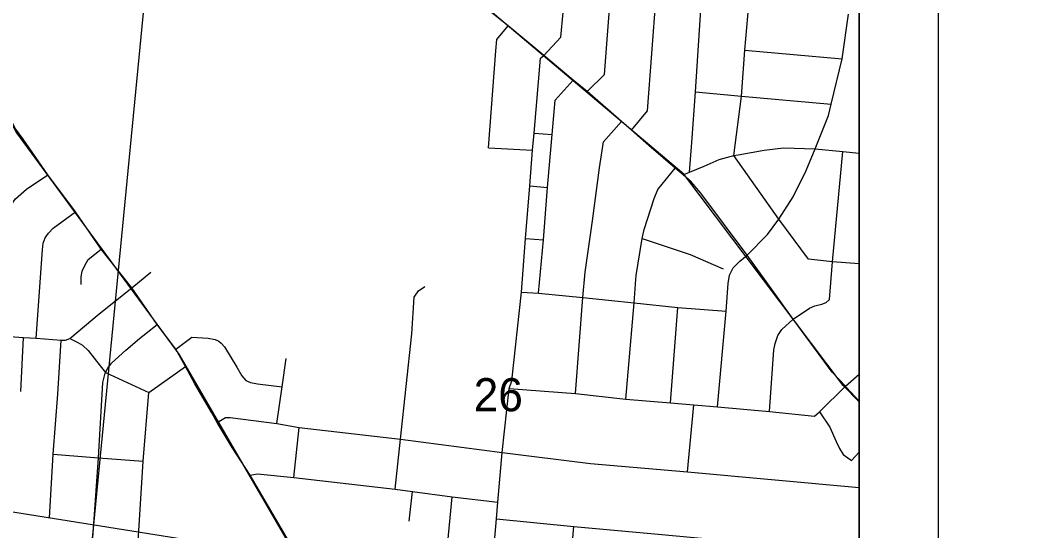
# Model space of a CAD drawing. Extents: x 0 to 34, y 0 to 22.
# Drawn here: x 7.838 to 9.127, y 16.149 to 16.794 of the extents above; entities that cross this region are included whole.
import ezdxf

# ---------------------------------------------------------------- set-up
doc = ezdxf.new("R2010")
doc.units = 0
for name, color, linetype in [('Default', 7, 'Continuous'), ('GM_X_City_Street', 7, 'Continuous'), ('GM_X_County_Road', 7, 'Continuous'), ('GM_X_Rail_Line', 7, 'Continuous'), ('GM_X_Section', 7, 'Continuous'), ('GM_X_Section_Text', 7, 'Continuous'), ('GM_X_State_Route', 7, 'Continuous'), ('GM_X_Township_Road', 7, 'Continuous'), ('SH_Data', 7, 'Continuous'), ('SH_Text', 7, 'Continuous')]:
    doc.layers.add(name, color=color, linetype=linetype)

msp = doc.modelspace()

# ---------------------------------------------------------------- linework, layer by layer
at = {"layer": 'Default'}
msp.add_lwpolyline([(8.9, 15.7814), (8.9, 16.8048), (8.0016, 16.8868), (7.9035, 15.8736)], close=True, dxfattribs=at)
at = {"layer": 'GM_X_City_Street'}
for p, q in [((8.7551, 16.7564), (8.8784, 16.7457)), ((8.4884, 16.6515), (8.5115, 16.6501)), ((8.6852, 16.6021), (8.688, 16.6398)), ((8.4308, 16.6329), (8.4866, 16.6299)), ((8.4829, 16.5851), (8.5056, 16.5827)), ((8.4774, 16.5183), (8.5004, 16.5168)), ((7.9795, 16.4558), (8.0034, 16.4757)), ((8.6609, 16.3104), (8.6702, 16.4312)), ((7.839, 16.3248), (7.8423, 16.3933)), ((8.9, 16.3125), (8.8838, 16.33)), ((8.6825, 16.2232), (8.6904, 16.308)), ((8.1844, 16.2161), (8.1912, 16.2795)), ((8.3305, 16.1607), (8.3347, 16.1985)), ((8.5321, 16.0763), (8.5389, 16.154))]:
    msp.add_line(p, q, dxfattribs=at)
for points in [[(8.9, 16.4865), (8.8662, 16.4889), (8.8359, 16.4923), (8.7983, 16.5429), (8.7412, 16.6234), (8.751, 16.6985), (8.7551, 16.7564), (8.7604, 16.814), (8.776, 16.9853), (8.7868, 17.1123), (8.7916, 17.1766), (8.8011, 17.2471), (8.8108, 17.3575), (8.8134, 17.4882), (8.8144, 17.504), (8.8153, 17.5125), (8.8617, 17.5828), (8.8723, 17.6093)], [(8.5554, 16.7041), (8.5774, 16.726), (8.5855, 16.8312), (8.5988, 17.0025), (8.6063, 17.1111), (8.6106, 17.167)], [(8.6116, 16.6556), (8.6318, 16.6797), (8.6429, 16.8253), (8.6561, 16.9964), (8.6684, 17.1592)], [(8.6978, 16.7817), (8.7003, 16.8196), (8.7037, 16.8601)], [(8.8838, 16.33), (8.8824, 16.3315), (8.8656, 16.3492), (8.8164, 16.4162), (8.7823, 16.464), (8.7583, 16.4972), (8.6994, 16.5756), (8.6873, 16.59), (8.6771, 16.5987), (8.667, 16.6073), (8.6336, 16.6362), (8.6116, 16.6556), (8.5992, 16.6662), (8.5554, 16.7041), (8.538, 16.7187), (8.5006, 16.7499), (8.4555, 16.7875), (8.3773, 16.8503)], [(8.5006, 16.7499), (8.5224, 16.7729), (8.5281, 16.8359)], [(8.7583, 16.4972), (8.784, 16.5233), (8.7983, 16.5429), (8.8163, 16.5712), (8.8327, 16.6043), (8.844, 16.6316), (8.861, 16.6738), (8.8646, 16.6881), (8.8784, 16.7457), (8.8865, 16.8022)], [(8.4308, 16.6329), (8.4401, 16.7558), (8.4411, 16.7699), (8.4555, 16.7875)], [(8.688, 16.6398), (8.6926, 16.704), (8.6978, 16.7817)], [(8.4086, 15.8203), (8.4148, 15.879), (8.42, 15.9362), (8.4311, 16.0521), (8.4407, 16.1639), (8.4425, 16.1849), (8.4481, 16.2479), (8.4567, 16.3286), (8.4603, 16.3382), (8.4723, 16.4504), (8.4774, 16.5183), (8.4829, 16.5851), (8.4866, 16.6299), (8.4884, 16.6515), (8.4965, 16.7464), (8.5006, 16.7499)], [(8.4942, 16.4491), (8.5004, 16.5168), (8.5056, 16.5827), (8.5115, 16.6501), (8.5152, 16.6934), (8.538, 16.7187)], [(8.6926, 16.704), (8.751, 16.6985), (8.8646, 16.6881)], [(8.5407, 16.3224), (8.5502, 16.4438), (8.5531, 16.476), (8.5622, 16.5409), (8.5712, 16.6078), (8.5763, 16.6405), (8.5992, 16.6662)], [(8.6771, 16.5987), (8.6852, 16.6021), (8.7038, 16.6099), (8.7225, 16.6183), (8.7412, 16.6234), (8.7469, 16.6244), (8.7795, 16.6302), (8.8042, 16.633), (8.844, 16.6316), (8.8791, 16.6286), (8.9, 16.6265)], [(8.7865, 16.2995), (8.7918, 16.3776), (8.7934, 16.3856), (8.797, 16.3959), (8.8021, 16.4035), (8.8164, 16.4162), (8.8369, 16.4302), (8.8437, 16.4333), (8.8526, 16.4354), (8.8579, 16.4375), (8.8621, 16.4412), (8.8662, 16.4889), (8.8791, 16.6286)], [(7.7859, 16.2596), (7.7949, 16.3964), (7.8011, 16.4591), (7.8063, 16.5164), (7.8121, 16.537), (7.8198, 16.5512), (7.832, 16.5685), (7.8462, 16.5808), (7.8732, 16.5991)], [(8.6046, 16.3153), (8.6152, 16.437), (8.6171, 16.4664), (8.6176, 16.4717), (8.6252, 16.5182), (8.6276, 16.5296), (8.6404, 16.569), (8.6452, 16.5804), (8.667, 16.6073)], [(7.2902, 16.5568), (7.2963, 16.5565), (7.3438, 16.5259), (7.4102, 16.4873), (7.4406, 16.4692), (7.4582, 16.4588), (7.4874, 16.4412), (7.5661, 16.4352), (7.6324, 16.4309), (7.7028, 16.4255), (7.716, 16.419), (7.74, 16.4055), (7.7495, 16.4004), (7.7616, 16.3995), (7.7949, 16.3964), (7.8014, 16.3961), (7.8423, 16.3933), (7.8584, 16.3922), (7.8899, 16.3899), (7.8952, 16.39), (7.9007, 16.392), (7.9381, 16.4233), (7.9795, 16.4558)], [(7.8584, 16.3922), (7.8663, 16.5041), (7.8673, 16.5125), (7.8696, 16.5191), (7.8738, 16.5252), (7.88, 16.5313), (7.9081, 16.5521)], [(8.6252, 16.5182), (8.686, 16.4983), (8.7278, 16.4802)], [(7.9154, 16.4604), (7.9154, 16.47), (7.9167, 16.4772), (7.92, 16.4844), (7.924, 16.4917), (7.9407, 16.505)], [(8.7205, 16.3054), (8.7314, 16.4264), (8.7339, 16.4616), (8.7358, 16.4719), (8.7402, 16.4811), (8.749, 16.4899), (8.7583, 16.4972)], [(8.3127, 16.2015), (8.3194, 16.2645), (8.3336, 16.398), (8.3366, 16.444), (8.342, 16.4523), (8.3503, 16.4577)], [(8.4723, 16.4504), (8.4942, 16.4491), (8.5502, 16.4438), (8.6152, 16.437), (8.6702, 16.4312), (8.7314, 16.4264)], [(7.9458, 16.3481), (7.946, 16.3491), (7.9488, 16.3544), (7.9537, 16.3607), (7.9719, 16.3771), (7.989, 16.3921), (8.0114, 16.4096)], [(8.0351, 16.3783), (8.0551, 16.3935), (8.076, 16.3922), (8.0848, 16.3905), (8.0895, 16.3885), (8.0926, 16.3858), (8.0966, 16.3814), (8.1122, 16.3557), (8.1186, 16.3445), (8.1237, 16.3388), (8.1294, 16.3364), (8.1385, 16.3347), (8.1696, 16.3307)], [(7.8751, 16.1649), (7.8799, 16.2458), (7.8858, 16.3215), (7.8899, 16.3899)], [(7.9007, 16.392), (7.9112, 16.3867), (7.9169, 16.3833), (7.9239, 16.3766), (7.9391, 16.3572), (7.946, 16.3491), (8.0008, 16.3238)], [(8.1629, 16.2842), (8.1696, 16.3307), (8.1747, 16.3665)], [(7.9052, 15.8092), (7.9207, 15.8088), (7.9324, 15.8106), (7.9429, 15.8151), (7.9514, 15.8196), (7.9596, 15.8305), (7.9655, 15.8422), (7.9671, 15.8605), (7.9737, 15.9464), (7.9855, 16.108), (7.9939, 16.2369), (8.0008, 16.3238), (8.0471, 16.3563)], [(7.9274, 16.1076), (7.9277, 16.1116), (7.9311, 16.1575), (7.9371, 16.2411), (7.9427, 16.3362), (7.9458, 16.3481)], [(8.8498, 16.299), (8.8824, 16.3315), (8.9, 16.3466)], [(8.4567, 16.3286), (8.5407, 16.3224), (8.6046, 16.3153), (8.6609, 16.3104), (8.6904, 16.308), (8.7205, 16.3054), (8.7865, 16.2995), (8.8434, 16.2936), (8.8498, 16.299), (8.8626, 16.2798), (8.8706, 16.2617), (8.8748, 16.2527), (8.8796, 16.2452), (8.8886, 16.2388), (8.8902, 16.2378), (8.9, 16.248)], [(8.0875, 16.2858), (8.0977, 16.2921), (8.1039, 16.2921), (8.1629, 16.2842), (8.1912, 16.2795), (8.3194, 16.2645), (8.4481, 16.2479), (8.5599, 16.234), (8.6825, 16.2232), (8.9, 16.2034)], [(7.8799, 16.2458), (7.9371, 16.2411), (7.9939, 16.2369)], [(8.1292, 16.2191), (8.1383, 16.2208), (8.1844, 16.2161), (8.3127, 16.2015), (8.3347, 16.1985), (8.3846, 16.1916), (8.4425, 16.1849)], [(8.3616, 15.9413), (8.372, 16.0594), (8.3846, 16.1916)], [(8.4407, 16.1639), (8.5389, 16.154), (8.6455, 16.1443), (8.7774, 16.1321), (8.8358, 16.1268), (8.9, 16.1214)]]:
    msp.add_lwpolyline(points, dxfattribs=at)
at = {"layer": 'GM_X_County_Road'}
for points in [[(8.0805, 16.2977), (8.059, 16.3344), (8.0471, 16.3563), (8.0351, 16.3783), (8.0114, 16.4096), (7.9795, 16.4558), (7.9407, 16.505), (7.9081, 16.5521), (7.8732, 16.5991), (7.842, 16.6441), (7.8312, 16.6583), (7.8252, 16.6711), (7.8202, 16.6844), (7.8183, 16.6949), (7.816, 16.7097), (7.8148, 16.7833), (7.8148, 16.8291)], [(8.1297, 16.2182), (8.1292, 16.2191), (8.1062, 16.254), (8.0875, 16.2858), (8.0805, 16.2977)], [(8.2453, 16.0168), (8.2448, 16.0176), (8.2306, 16.0421), (8.1899, 16.1153), (8.1297, 16.2182)]]:
    msp.add_lwpolyline(points, dxfattribs=at)
at = {"layer": 'GM_X_Rail_Line'}
for points in [[(7.8169, 16.8999), (7.8105, 16.8874), (7.814, 16.6995), (7.8204, 16.6764), (7.8335, 16.6519), (8.0389, 16.3719), (8.2579, 15.9951), (8.7281, 15.1727), (8.8328, 15.0366), (8.8456, 15.016), (8.8469, 15.007)], [(8.9, 16.3116), (8.8798, 16.3324), (8.6781, 16.5996), (8.3819, 16.8496), (7.8287, 16.9051), (7.8169, 16.8999)]]:
    msp.add_lwpolyline(points, dxfattribs=at)
at = {"layer": 'GM_X_Section'}
msp.add_lwpolyline([(7.0031, 16.9763), (8.0016, 16.8868), (7.9035, 15.8736), (6.9063, 15.9571)], close=True, dxfattribs=at)
at = {"layer": 'GM_X_State_Route'}
msp.add_lwpolyline([(8.9, 15.5977), (8.9, 20.2522)], dxfattribs=at)
at = {"layer": 'GM_X_Township_Road'}
msp.add_lwpolyline([(8.9, 14.1), (8.9, 20.9)], dxfattribs=at)
at = {"layer": 'SH_Data'}
for p, q in [((9, 21), (9, 14)), ((8.9, 20.9), (8.9, 14.1))]:
    msp.add_line(p, q, dxfattribs=at)
at = {"layer": 'SH_Text'}
msp.add_lwpolyline([(5.5598, 16.5345), (9.346, 15.9306), (10.7296, 15.939), (10.7249, 15.654), (9.3684, 15.6583)], close=True, dxfattribs=at)

# ---------------------------------------------------------------- texts
at = {"layer": 'GM_X_Section_Text'}
msp.add_text('26', height=0.04186, rotation=0, dxfattribs=at).set_placement((8.412, 16.2999))

doc.saveas('drawing.dxf')
